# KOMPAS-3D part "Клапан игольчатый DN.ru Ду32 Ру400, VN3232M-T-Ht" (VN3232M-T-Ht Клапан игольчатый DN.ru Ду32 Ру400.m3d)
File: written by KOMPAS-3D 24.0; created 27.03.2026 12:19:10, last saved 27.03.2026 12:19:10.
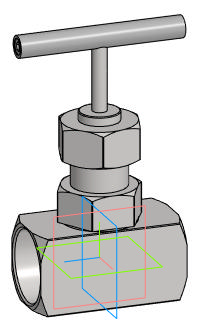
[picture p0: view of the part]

Document properties: Автор: Илья; Полное имя файла: D:\Обмен\Заказы с фриланса\DN.ru\VNxxM-T-Ht Клапан игольчатый DN.ru Ду8-50 Ру400\VN3232M-T-Ht Клапан игольчатый DN.ru Ду8-50 Ру400\DN32\VN3232M-T-Ht Клапан игольчатый DN.ru Ду32 Ру400.m3d

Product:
- Body: Body10  | qty 1
    Масса: 1.287778
- Part/product: Клапан игольчатый DN.ru Ду32 Ру400  | designation VN3232M-T-Ht
    Масса: 1
    Раздел спецификации: Прочие изделия
    Примечание: D090-02134

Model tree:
1. Body10  (labels: Body10)

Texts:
  VN3232M-T-Ht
